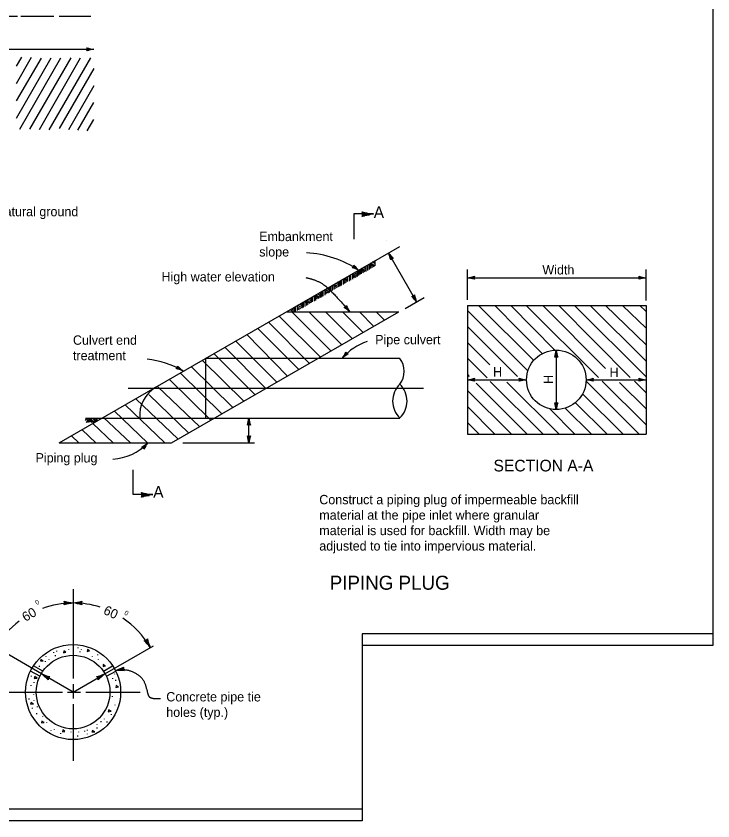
# Model space of a CAD drawing. Extents: x 0 to 390, y 0 to 265.
# Drawn here: x 241.1 to 390, y 0 to 172.1 of the extents above; entities that cross this region are included whole.
import ezdxf

# ---------------------------------------------------------------- set-up
doc = ezdxf.new("R2010")
doc.units = 0
doc.layers.add('D_Details', color=7, linetype='Continuous')
doc.layers.add('Default', color=7, linetype='Continuous')

msp = doc.modelspace()

# ---------------------------------------------------------------- linework, layer by layer
at = {"layer": 'D_Details'}
for p, q in [((234.15, 172.1), (241.35, 172.1)), ((242.05, 172.1), (249.15, 172.1)), ((250.25, 172.1), (257.05, 172.1)), ((223.85, 165), (257.65, 165)), ((241.15, 157.7), (244.35, 163.3)), ((241.15, 161.4), (242.25, 163.3)), ((241.15, 150.3), (248.55, 163.2)), ((241.15, 154), (246.45, 163.1)), ((241.85, 147.9), (250.65, 163.2)), ((252.75, 163.2), (243.95, 147.9)), ((254.75, 163.1), (245.95, 147.8)), ((256.95, 163.2), (248.05, 147.8)), ((257.65, 160.9), (250.25, 148.1)), ((257.65, 157.2), (252.25, 147.8)), ((254.25, 147.7), (257.65, 153.6)), ((256.25, 147.6), (257.65, 150)), ((320.23, 124.21), (320.23, 124.21)), ((250.27, 80.82), (323.11, 122.82)), ((320.67, 121.41), (326.67, 111.02)), ((316.21, 117.72), (316.21, 118.92)), ((316.61, 117.92), (316.61, 119.12)), ((316.91, 118.12), (316.91, 119.32)), ((317.81, 118.72), (316.91, 119.22)), ((317.61, 118.52), (316.91, 118.92)), ((317.81, 119.12), (317.21, 119.52)), ((317.81, 119.52), (317.51, 119.62)), ((317.81, 118.72), (317.81, 119.82)), ((313.91, 116.82), (313.31, 117.22)), ((314.01, 117.22), (313.71, 117.42)), ((314.01, 116.42), (314.01, 117.62)), ((314.31, 116.62), (314.31, 117.72)), ((314.61, 116.82), (314.61, 117.92)), ((314.91, 117.02), (314.91, 118.12)), ((315.91, 117.62), (314.91, 118.12)), ((315.61, 117.42), (314.91, 117.82)), ((315.31, 117.22), (315.01, 117.42)), ((315.91, 118.02), (315.31, 118.32)), ((315.91, 118.42), (315.61, 118.52)), ((315.91, 117.52), (315.91, 118.72)), ((317.31, 118.32), (316.91, 118.52)), ((337.52, 111.46), (337.52, 117.91)), ((375.72, 111.26), (375.72, 117.91)), ((310.01, 114.22), (310.01, 115.32)), ((310.31, 114.32), (310.31, 115.42)), ((310.61, 114.52), (310.61, 115.72)), ((311.01, 114.72), (311.01, 115.82)), ((311.91, 115.32), (311.01, 115.82)), ((311.71, 115.12), (311.01, 115.52)), ((311.91, 115.72), (311.31, 116.02)), ((311.91, 116.12), (311.71, 116.22)), ((311.91, 115.32), (311.91, 116.42)), ((312.01, 116.42), (312.01, 116.42)), ((312.31, 115.42), (312.31, 116.62)), ((312.61, 115.62), (312.61, 116.82)), ((313.01, 115.82), (313.01, 117.02)), ((314.01, 116.42), (313.01, 117.02)), ((313.71, 116.22), (313.01, 116.62)), ((313.41, 116.12), (313.01, 116.32)), ((337.52, 116.14), (375.72, 116.14)), ((307.11, 112.42), (307.11, 113.62)), ((308.01, 113.02), (307.11, 113.62)), ((308.01, 113.52), (307.41, 113.82)), ((308.01, 113.82), (307.81, 114.02)), ((308.01, 113.02), (308.01, 114.22)), ((308.31, 113.22), (308.31, 114.32)), ((308.71, 113.42), (308.71, 114.52)), ((309.01, 113.62), (309.01, 114.72)), ((310.01, 114.22), (309.01, 114.72)), ((309.71, 114.02), (309.01, 114.42)), ((309.41, 113.82), (309.01, 114.02)), ((310.01, 114.62), (309.41, 114.92)), ((310.01, 115.02), (309.71, 115.12)), ((311.41, 114.92), (311.01, 115.22)), ((304.11, 110.82), (304.11, 111.92)), ((304.41, 111.02), (304.41, 112.02)), ((304.81, 111.12), (304.81, 112.32)), ((305.11, 111.32), (305.11, 112.52)), ((306.11, 111.92), (305.11, 112.42)), ((305.81, 111.72), (305.11, 112.12)), ((306.01, 112.32), (305.51, 112.72)), ((306.11, 112.72), (305.81, 112.92)), ((306.11, 111.92), (306.11, 113.02)), ((306.11, 113.02), (306.11, 113.02)), ((306.41, 112.02), (306.41, 113.22)), ((306.71, 112.22), (306.71, 113.42)), ((307.81, 112.82), (307.11, 113.22)), ((307.41, 112.72), (307.11, 112.92)), ((324.19, 109.59), (328.29, 111.95)), ((301.21, 109.12), (301.21, 110.22)), ((302.21, 109.72), (301.21, 110.22)), ((302.21, 110.12), (301.61, 110.42)), ((302.21, 110.42), (301.91, 110.62)), ((302.21, 109.62), (302.21, 110.82)), ((302.51, 109.82), (302.51, 110.92)), ((302.81, 110.02), (302.81, 111.12)), ((303.21, 110.22), (303.11, 111.32)), ((303.81, 110.62), (303.11, 111.02)), ((304.11, 110.82), (303.21, 111.32)), ((303.51, 110.42), (303.21, 110.72)), ((304.11, 111.22), (303.51, 111.52)), ((304.11, 111.62), (303.81, 111.72)), ((305.51, 111.62), (305.11, 111.82)), ((337.52, 110.25), (337.52, 82.73)), ((337.52, 110.25), (375.72, 110.25)), ((339.89, 110.25), (351.72, 98.43)), ((343.4, 110.25), (353.52, 99.93)), ((346.81, 110.25), (356.22, 100.63)), ((350.09, 110.25), (365.52, 94.83)), ((353.66, 110.25), (367.02, 96.73)), ((357.04, 110.25), (372.32, 94.83)), ((360.39, 110.25), (375.72, 94.93)), ((363.79, 110.25), (375.72, 98.33)), ((367.02, 110.25), (375.72, 101.83)), ((370.68, 110.25), (375.72, 105.38)), ((374.35, 110.25), (375.72, 108.93)), ((375.72, 110.25), (375.72, 82.73)), ((274.3, 80.82), (322.9, 108.84)), ((298.88, 108.84), (322.9, 108.84)), ((300.21, 108.92), (299.61, 109.32)), ((300.21, 109.32), (299.91, 109.52)), ((300, 108.84), (308.38, 100.47)), ((300.21, 109.62), (300.21, 109.62)), ((300.51, 108.72), (300.51, 109.82)), ((300.81, 108.92), (300.81, 110.02)), ((301.91, 109.52), (301.21, 109.82)), ((301.61, 109.32), (301.21, 109.52)), ((303.61, 108.84), (310.66, 101.79)), ((307.22, 108.84), (312.95, 103.11)), ((310.82, 108.84), (315.24, 104.43)), ((314.43, 108.84), (317.53, 105.75)), ((318.03, 108.84), (319.81, 107.06)), ((337.52, 109.13), (350.42, 96.23)), ((297.3, 107.94), (306.09, 99.15)), ((292.71, 105.32), (301.51, 96.51)), ((295.02, 106.62), (303.8, 97.83)), ((337.52, 105.73), (348.22, 95.03)), ((290.41, 104.02), (299.09, 95.12)), ((288.01, 102.62), (296.82, 93.81)), ((337.52, 102.33), (342.32, 97.53)), ((283.31, 99.92), (292.13, 91.1)), ((285.71, 101.22), (294.31, 92.62)), ((356.52, 100.63), (356.52, 87.93)), ((280.93, 98.49), (289.76, 89.73)), ((281.51, 98.92), (305.68, 98.92)), ((281.51, 98.92), (281.51, 86.12)), ((305.68, 98.92), (323.11, 98.92)), ((337.52, 98.93), (341.72, 94.73)), ((278.57, 97.13), (287.4, 88.37)), ((276.2, 95.77), (285.05, 87.02)), ((337.52, 95.43), (337.92, 95.03)), ((273.81, 94.39), (282.69, 85.66)), ((337.52, 94.33), (350.12, 94.33)), ((339.42, 93.63), (350.32, 82.73)), ((342.42, 93.93), (353.72, 82.73)), ((345.92, 93.83), (357.12, 82.73)), ((362.92, 94.33), (375.72, 94.33)), ((362.92, 94.03), (374.22, 82.73)), ((366.32, 94.03), (375.72, 84.73)), ((370.02, 93.73), (375.72, 88.13)), ((373.22, 94.03), (375.72, 91.53)), ((265, 92.52), (328.11, 92.52)), ((271.27, 92.93), (280.3, 84.28)), ((337.52, 92.03), (346.92, 82.73)), ((362.12, 91.33), (370.82, 82.73)), ((266.67, 90.27), (275.7, 81.63)), ((269.51, 91.09), (278, 82.95)), ((264.37, 88.95), (272.85, 80.82)), ((337.52, 88.63), (343.42, 82.73)), ((355.12, 88.13), (360.52, 82.73)), ((358.42, 88.23), (364.02, 82.73)), ((360.62, 89.43), (367.42, 82.73)), ((255.91, 85.62), (256.21, 86.12)), ((255.91, 86.12), (255.91, 86.12)), ((255.91, 86.12), (259.46, 86.12)), ((256.11, 85.22), (256.61, 86.12)), ((256.41, 85.22), (257.01, 86.12)), ((257.61, 85.22), (257.01, 86.12)), ((257.81, 85.52), (257.51, 86.12)), ((257.61, 85.22), (258.11, 86.12)), ((258.01, 85.92), (257.81, 86.12)), ((257.91, 85.22), (258.51, 86.12)), ((259.46, 86.12), (283.49, 86.12)), ((259.77, 86.29), (265.48, 80.82)), ((262.07, 87.62), (269.17, 80.82)), ((283.49, 86.12), (323.11, 86.12)), ((290.82, 80.82), (290.82, 86.12)), ((256.91, 85.22), (256.71, 85.52)), ((257.31, 85.22), (256.81, 85.92)), ((257.47, 84.97), (261.8, 80.82)), ((337.52, 85.23), (340.02, 82.73)), ((255.17, 83.64), (258.11, 80.82)), ((337.52, 82.73), (375.72, 82.73)), ((252.87, 82.31), (254.43, 80.82)), ((250.27, 80.82), (274.3, 80.82)), ((276.67, 80.82), (292.02, 80.82)), ((253.25, 49.55), (253.25, 30.45)), ((246.45, 31.45), (235.25, 37.95)), ((249.75, 36.25), (249.75, 36.35)), ((252.35, 36.65), (252.35, 36.75)), ((254.35, 36.95), (254.35, 37.05)), ((254.75, 36.05), (254.75, 36.25)), ((255.05, 36.65), (255.05, 36.75)), ((260.05, 31.45), (270.45, 37.45)), ((247.45, 35.05), (247.45, 35.15)), ((248.15, 34.45), (248.15, 34.55)), ((249.15, 35.95), (249.15, 36.05)), ((249.45, 35.25), (249.45, 35.45)), ((257.35, 35.05), (257.35, 35.15)), ((258.55, 35.45), (258.55, 35.55)), ((258.65, 34.45), (258.65, 34.55)), ((246.75, 32.05), (244.75, 33.15)), ((246.05, 32.95), (246.05, 33.15)), ((247.35, 34.05), (247.35, 34.15)), ((259.75, 32.05), (261.65, 33.15)), ((246.15, 30.95), (244.15, 32.05)), ((244.35, 30.85), (244.35, 31.05)), ((253.25, 27.55), (246.45, 31.45)), ((253.25, 27.55), (260.05, 31.45)), ((260.35, 30.95), (262.35, 32.05)), ((262.15, 31.35), (262.15, 31.45)), ((244.95, 29.55), (244.95, 29.65)), ((261.75, 30.35), (261.75, 30.55)), ((262.35, 29.95), (262.35, 30.15)), ((239.55, 27.55), (250.95, 27.55)), ((244.25, 28.85), (244.25, 29.05)), ((252.05, 27.55), (253.25, 27.55)), ((253.25, 29.25), (253.25, 26.15)), ((253.55, 27.55), (254.85, 27.55)), ((255.95, 27.55), (267.55, 27.55)), ((243.85, 25.95), (243.85, 26.15)), ((244.85, 26.95), (244.85, 27.05)), ((244.95, 25.75), (244.95, 25.85)), ((261.65, 26.55), (261.65, 26.65)), ((244.55, 24.05), (244.55, 24.15)), ((245.65, 24.35), (245.65, 24.45)), ((253.25, 24.95), (253.25, 12.85)), ((262.25, 24.75), (262.25, 24.85)), ((245.45, 22.85), (245.45, 23.05)), ((261.45, 22.65), (261.45, 22.85)), ((246.75, 22.25), (246.75, 22.35)), ((247.65, 20.95), (247.65, 21.05)), ((259.25, 21.15), (259.25, 21.35)), ((259.95, 21.75), (259.95, 21.85)), ((260.55, 21.05), (260.55, 21.25)), ((248.55, 19.25), (248.55, 19.35)), ((249.25, 19.45), (249.25, 19.55)), ((252.85, 18.95), (252.85, 19.05)), ((254.45, 18.95), (254.45, 19.05)), ((255.75, 19.15), (255.75, 19.25)), ((256.35, 19.35), (256.35, 19.45)), ((258.35, 20.55), (258.35, 20.65)), ((258.35, 19.75), (258.35, 19.95)), ((250.65, 18.65), (250.65, 18.75)), ((254.25, 18.05), (254.25, 18.25)), ((256.35, 18.55), (256.35, 18.65))]:
    msp.add_line(p, q, dxfattribs=at)
for points in [[(317.43, 129.81), (313.23, 129.81), (313.23, 124.41)], [(315.03, 130.21), (315.13, 130.21)], [(315.03, 130.11), (315.53, 130.11)], [(315.03, 129.41), (315.53, 129.41)], [(315.03, 129.31), (315.13, 129.31)], [(315.13, 130.01), (316.03, 130.01)], [(315.13, 129.91), (316.63, 129.91)], [(315.13, 129.81), (315.13, 129.81), (317.43, 129.81), (317.43, 129.81)], [(315.13, 129.61), (316.63, 129.61)], [(315.13, 129.51), (316.03, 129.51)], [(270.28, 69.79), (266.08, 69.79), (266.08, 75.09)], [(267.88, 70.19), (267.98, 70.19)], [(267.88, 70.09), (268.38, 70.09)], [(267.88, 69.39), (268.38, 69.39)], [(267.88, 69.29), (267.98, 69.29)], [(267.98, 69.99), (268.88, 69.99)], [(267.98, 69.89), (269.48, 69.89)], [(267.98, 69.79), (267.98, 69.79), (270.28, 69.79), (270.28, 69.79)], [(267.98, 69.59), (269.48, 69.59)], [(267.98, 69.49), (268.88, 69.49)]]:
    msp.add_lwpolyline(points, dxfattribs=at)
for points in [[(251.15, 35.95), (251.65, 36.05), (251.25, 36.35)], [(256.25, 36.25), (256.75, 36.35), (256.35, 36.65)], [(246.25, 34.25), (246.85, 34.25), (246.35, 34.55)], [(259.65, 33.05), (260.15, 33.15), (259.65, 33.45)], [(244.95, 30.45), (245.55, 30.55), (245.05, 30.85)], [(262.35, 28.55), (262.95, 28.65), (262.45, 28.95)], [(244.15, 24.95), (244.75, 25.05), (244.25, 25.35)], [(260.75, 23.35), (261.35, 23.45), (260.85, 23.75)], [(246.45, 20.95), (247.05, 21.05), (246.55, 21.35)], [(250.95, 19.05), (251.45, 19.15), (251.05, 19.45)], [(257.25, 19.05), (257.85, 19.05), (257.35, 19.35)]]:
    msp.add_lwpolyline(points, close=True, dxfattribs=at)
for centre, radius in [((356.52, 94.32), 6.36), ((253.24, 27.55), 10.16), ((253.24, 27.55), 7.87)]:
    msp.add_circle(centre, radius, dxfattribs=at)
for centre, radius, start, end in [((255.53, 165), 0.699, 333.215, 26.785), ((259.22, 176.14), 11.25, 254.1865, 262), ((259.22, 153.86), 11.25, 98, 105.8117), ((259.22, 176.14), 11.35, 254.5699, 258.999), ((259.22, 153.86), 11.35, 101.001, 105.4301), ((259.22, 176.14), 11.45, 254.8291, 256.6406), ((259.22, 153.86), 11.45, 103.3594, 105.1709), ((314, 129.76), 1.13, 333.215, 26.785), ((319.95, 147.73), 18.14, 254.1865, 262), ((319.95, 111.8), 18.14, 98, 105.8117), ((302.07, 99.65), 21.83, 55.8846, 87.2459), ((310.21, 117.28), 11.25, 13.7646, 21.5781), ((329.59, 128.27), 11.25, 217.5781, 225.3898), ((329.59, 128.27), 11.35, 220.5791, 225.0082), ((310.21, 117.28), 11.35, 14.148, 18.5771), ((329.59, 128.27), 11.45, 222.9374, 224.749), ((310.21, 117.28), 11.45, 14.4072, 16.2187), ((312.55, 118.91), 0.699, 299.0996, 352.6696), ((321.86, 126.06), 11.25, 220.0711, 227.8846), ((321.72, 119.57), 0.699, 92.7931, 146.3631), ((309.36, 107.62), 11.25, 63.8846, 71.6963), ((309.36, 107.62), 11.35, 66.8856, 71.3147), ((309.36, 107.62), 11.45, 69.244, 71.0555), ((321.86, 126.06), 11.45, 220.7137, 222.5252), ((321.86, 126.06), 11.35, 220.4545, 224.8836), ((335.95, 127.28), 11.25, 278, 285.8117), ((335.95, 105), 11.25, 74.1865, 82), ((335.95, 127.28), 11.35, 281.001, 285.4301), ((335.95, 105), 11.35, 74.5699, 78.999), ((335.95, 127.28), 11.45, 283.3594, 285.1709), ((335.95, 105), 11.45, 74.8291, 76.6406), ((339.64, 116.14), 0.699, 153.215, 206.785), ((373.59, 116.14), 0.699, 333.215, 26.785), ((377.28, 127.28), 11.25, 254.1865, 262), ((377.28, 105), 11.25, 98, 105.8117), ((377.28, 127.28), 11.35, 254.5699, 258.999), ((377.28, 105), 11.35, 101.001, 105.4301), ((377.28, 127.28), 11.45, 254.8291, 256.6406), ((377.28, 105), 11.45, 103.3594, 105.1709), ((325.6, 112.86), 0.699, 273.2016, 326.7716), ((317.8, 104.09), 11.25, 37.9866, 45.7983), ((317.8, 104.09), 11.35, 40.9876, 45.4167), ((317.8, 104.09), 11.45, 43.346, 45.1575), ((337.1, 115.23), 11.45, 194.8157, 196.6273), ((337.1, 115.23), 11.35, 194.5565, 198.9856), ((337.1, 115.23), 11.25, 194.1732, 201.9866), ((310.98, 110.45), 0.699, 284.266, 337.836), ((321.81, 114.98), 11.25, 205.2375, 213.051), ((305.01, 100.35), 11.25, 49.051, 56.8627), ((305.01, 100.35), 11.35, 52.052, 56.4811), ((305.01, 100.35), 11.45, 54.4104, 56.2219), ((321.81, 114.98), 11.45, 205.8801, 207.6917), ((321.81, 114.98), 11.35, 205.6209, 210.05), ((319.39, 91.96), 11.04, 107.2977, 140.6943), ((301.23, 104.8), 11.25, 328.6943, 336.506), ((318.47, 90.68), 11.25, 124.8809, 132.6943), ((301.23, 104.8), 11.35, 331.6953, 336.1244), ((318.47, 90.68), 11.35, 125.2642, 129.6933), ((301.23, 104.8), 11.45, 334.0537, 335.8652), ((318.47, 90.68), 11.45, 125.5234, 127.335), ((312.19, 100.6), 0.699, 203.9093, 257.4793), ((345.38, 102.2), 11.25, 344.1865, 352), ((345.38, 102.2), 11.35, 344.5699, 348.999), ((367.66, 102.2), 11.25, 188, 195.8117), ((367.66, 102.2), 11.35, 191.001, 195.4301), ((266.75, 78.3), 20.54, 60.9848, 83.526), ((319.5, 96.14), 4.52, 322.6781, 37.3219), ((356.52, 98.51), 0.699, 63.215, 116.785), ((345.38, 102.2), 11.45, 344.8291, 346.6406), ((367.66, 102.2), 11.45, 193.3594, 195.1709), ((274.86, 97.29), 0.699, 304.1998, 357.7698), ((272.68, 85.76), 11.25, 68.9848, 76.7965), ((272.68, 85.76), 11.35, 71.9858, 76.4149), ((272.68, 85.76), 11.45, 74.3442, 76.1558), ((283.49, 105.24), 11.45, 225.8139, 227.6255), ((283.49, 105.24), 11.35, 225.5548, 229.9838), ((283.49, 105.24), 11.25, 225.1714, 232.9848), ((326.51, 89.78), 4.97, 133.3358, 226.6642), ((319.57, 89.78), 5.05, 314.2869, 45.7131), ((335.95, 105.47), 11.25, 278, 285.8117), ((335.95, 105.47), 11.25, 278, 285.8117), ((335.95, 83.19), 11.25, 74.1865, 82), ((335.95, 83.19), 11.25, 74.1865, 82), ((335.95, 105.47), 11.35, 281.001, 285.4301), ((335.95, 105.47), 11.35, 281.001, 285.4301), ((335.95, 83.19), 11.35, 74.5699, 78.999), ((335.95, 83.19), 11.35, 74.5699, 78.999), ((335.95, 105.47), 11.45, 283.3594, 285.1709), ((335.95, 105.47), 11.45, 283.3594, 285.1709), ((335.95, 83.19), 11.45, 74.8291, 76.6406), ((335.95, 83.19), 11.45, 74.8291, 76.6406), ((339.64, 94.33), 0.699, 153.215, 206.785), ((339.64, 94.33), 0.699, 153.215, 206.785), ((347.99, 94.33), 0.699, 333.215, 26.785), ((351.68, 105.47), 11.25, 254.1865, 262), ((351.68, 83.19), 11.25, 98, 105.8117), ((351.68, 105.47), 11.35, 254.5699, 258.999), ((351.68, 83.19), 11.35, 101.001, 105.4301), ((351.68, 105.47), 11.45, 254.8291, 256.6406), ((351.68, 83.19), 11.45, 103.3594, 105.1709), ((361.35, 105.47), 11.25, 278, 285.8117), ((361.35, 105.47), 11.25, 278, 285.8117), ((361.35, 83.19), 11.25, 74.1865, 82), ((361.35, 83.19), 11.25, 74.1865, 82), ((361.35, 105.47), 11.35, 281.001, 285.4301), ((361.35, 105.47), 11.35, 281.001, 285.4301), ((361.35, 83.19), 11.35, 74.5699, 78.999), ((361.35, 83.19), 11.35, 74.5699, 78.999), ((361.35, 105.47), 11.45, 283.3594, 285.1709), ((361.35, 105.47), 11.45, 283.3594, 285.1709), ((361.35, 83.19), 11.45, 74.8291, 76.6406), ((361.35, 83.19), 11.45, 74.8291, 76.6406), ((365.04, 94.33), 0.699, 153.215, 206.785), ((365.04, 94.33), 0.699, 153.215, 206.785), ((373.59, 94.33), 0.699, 333.215, 26.785), ((377.28, 105.47), 11.25, 254.1865, 262), ((373.59, 94.33), 0.699, 333.215, 26.785), ((377.28, 105.47), 11.25, 254.1865, 262), ((377.28, 83.19), 11.25, 98, 105.8117), ((377.28, 83.19), 11.25, 98, 105.8117), ((377.28, 105.47), 11.35, 254.5699, 258.999), ((377.28, 105.47), 11.35, 254.5699, 258.999), ((377.28, 83.19), 11.35, 101.001, 105.4301), ((377.28, 83.19), 11.35, 101.001, 105.4301), ((377.28, 105.47), 11.45, 254.8291, 256.6406), ((377.28, 105.47), 11.45, 254.8291, 256.6406), ((377.28, 83.19), 11.45, 103.3594, 105.1709), ((377.28, 83.19), 11.45, 103.3594, 105.1709), ((274.45, 86.71), 6.99, 120.0001, 184.8262), ((356.52, 90.05), 0.699, 243.215, 296.785), ((345.38, 86.36), 11.25, 8, 15.8117), ((345.38, 86.36), 11.35, 11.001, 15.4301), ((345.38, 86.36), 11.45, 13.3594, 15.1709), ((367.66, 86.36), 11.25, 164.1865, 172), ((367.66, 86.36), 11.35, 164.5699, 168.999), ((367.66, 86.36), 11.45, 164.8291, 166.6406), ((279.68, 87.68), 11.25, 344.1865, 352), ((301.96, 87.68), 11.25, 188, 195.8117), ((290.82, 83.99), 0.699, 63.215, 116.785), ((279.68, 87.68), 11.35, 344.5699, 348.999), ((279.68, 87.68), 11.45, 344.8291, 346.6406), ((301.96, 87.68), 11.35, 191.001, 195.4301), ((301.96, 87.68), 11.45, 193.3594, 195.1709), ((290.82, 82.94), 0.699, 243.215, 296.785), ((279.68, 79.25), 11.25, 8, 15.8117), ((279.68, 79.25), 11.35, 11.001, 15.4301), ((279.68, 79.25), 11.45, 13.3594, 15.1709), ((301.96, 79.25), 11.25, 164.1865, 172), ((301.96, 79.25), 11.35, 164.5699, 168.999), ((301.96, 79.25), 11.45, 164.8291, 166.6406), ((261.13, 88.38), 11.03, 273.067, 316.7341), ((262.13, 89.59), 11.25, 300.9206, 308.7341), ((267.71, 79.27), 0.699, 19.9491, 73.519), ((262.13, 89.59), 11.35, 301.304, 305.7331), ((262.13, 89.59), 11.45, 301.5631, 303.3747), ((278.36, 74.32), 11.45, 150.0934, 151.905), ((278.36, 74.32), 11.35, 147.735, 152.1641), ((278.36, 74.32), 11.25, 144.734, 152.5457), ((266.85, 69.75), 1.13, 333.215, 26.785), ((272.8, 87.71), 18.14, 254.1865, 262), ((272.8, 51.78), 18.14, 98, 105.8117), ((253.24, 27.55), 19.05, 90.0703, 110.1632), ((255.16, 60.53), 14.06, 254.2568, 262.0703), ((250.56, 46.6), 0.874, 333.2853, 26.8553), ((255.19, 32.68), 14.06, 98.0703, 105.882), ((255.16, 60.53), 14.19, 254.6402, 259.0693), ((255.19, 32.68), 14.19, 101.0713, 105.5004), ((255.16, 60.53), 14.31, 254.8994, 256.7109), ((255.19, 32.68), 14.31, 103.4297, 105.2412), ((251.3, 60.53), 14.06, 277.9729, 285.7846), ((253.24, 27.55), 19.05, 72.2166, 89.9729), ((251.28, 32.68), 14.06, 74.1594, 81.9729), ((251.3, 60.53), 14.19, 280.9739, 285.403), ((251.28, 32.68), 14.19, 74.5428, 78.9719), ((251.3, 60.53), 14.31, 283.3322, 285.1438), ((251.28, 32.68), 14.31, 74.802, 76.6135), ((255.9, 46.6), 0.874, 153.1879, 206.7579), ((253.24, 27.55), 19.05, 30.1316, 56.1425), ((253.24, 27.55), 19.05, 127.2781, 150.0252), ((268.38, 39.41), 0.874, 273.3466, 326.9166), ((258.65, 28.43), 14.06, 38.1316, 45.9433), ((258.65, 28.43), 14.19, 41.1326, 45.5617), ((258.65, 28.43), 14.31, 43.491, 45.3025), ((282.74, 42.41), 14.31, 194.9607, 196.7722), ((282.74, 42.41), 14.19, 194.7015, 199.1306), ((282.74, 42.41), 14.06, 194.3181, 202.1316), ((257.6, 45.42), 14.06, 289.3099, 297.1216), ((257.6, 45.42), 14.19, 292.3109, 296.74), ((264.86, 32.67), 0.874, 164.5249, 218.0949), ((237.83, 20.34), 14.06, 44.351, 52.1645), ((251.68, 44.5), 14.06, 248.1645, 255.9761), ((251.68, 44.5), 14.19, 251.1655, 255.5945), ((237.83, 20.34), 14.19, 44.7344, 49.1635), ((254.82, 44.5), 14.06, 284.0221, 291.8355), ((254.82, 44.5), 14.19, 284.4055, 288.8345), ((268.68, 20.34), 14.19, 130.8365, 135.2656), ((268.68, 20.34), 14.06, 127.8355, 135.6472), ((263.07, 18.11), 14.06, 85.4965, 93.3099), ((263.07, 18.11), 14.19, 85.8799, 90.3089), ((257.6, 45.42), 14.31, 294.6693, 296.4809), ((263.07, 18.11), 14.31, 86.139, 87.9506), ((237.83, 20.34), 14.31, 44.9935, 46.8051), ((251.68, 44.5), 14.31, 253.5238, 255.3354), ((248.76, 30.13), 0.874, 123.3795, 176.9495), ((257.75, 30.13), 0.874, 3.0505, 56.6205), ((254.82, 44.5), 14.31, 284.6646, 286.4762), ((268.68, 20.34), 14.31, 133.1949, 135.0065)]:
    msp.add_arc(centre, radius, start, end, dxfattribs=at)
for points in [[(302.99, 116.17), (305.32, 115.73), (308.38, 113.55), (312.38, 108.84)], [(262.25, 32.15), (263.25, 32.35), (264.85, 32.35), (266.85, 31.55), (268.35, 30.15), (268.95, 28.25), (269.35, 26.55), (270.05, 26.25), (270.85, 26.15), (271.95, 26.15)]]:
    msp.add_open_spline(points, degree=2, dxfattribs=at)
at = {"layer": 'Default'}
for points in [[(0, 265), (326.25, 265), (326.25, 255), (390, 255), (390, 37.5), (315, 37.5), (315, 0), (0, 0)], [(0, 262.5), (326.25, 262.5), (326.25, 252.5), (390, 252.5), (390, 40), (315, 40), (315, 2.5), (0, 2.5)]]:
    msp.add_lwpolyline(points, close=True, dxfattribs=at)

# ---------------------------------------------------------------- texts
at = {"layer": 'D_Details'}
for s, height, p in [('Natural ground', 2, (236.66, 129.3)), ('A', 2.5, (317.49, 128.91)), ('Embankment', 2, (293.02, 123.99)), ('slope', 2, (293.02, 120.69)), ('Width', 2, (353.55, 116.85)), ('High water elevation', 2, (272.13, 115.36)), ('Culvert end', 2, (253.21, 101.82)), ('Pipe culvert', 2, (317.81, 101.92)), ('treatment', 2, (253.21, 98.52)), ('H', 2, (343.02, 95.03)), ('H', 2, (367.92, 94.93)), ('Piping plug', 2, (245.21, 76.65)), ('SECTION A-A', 2.5002, (343.1, 74.73)), ('A', 2.5, (270.35, 69.1)), ('Construct a piping plug of impermeable backfill ', 2, (305.86, 67.71)), ('material at the pipe inlet where granular ', 2, (305.86, 64.41)), ('material is used for backfill. Width may be', 2, (305.86, 61.11)), ('adjusted to tie into impervious material.', 2, (305.86, 57.81)), ('PIPING PLUG', 3, (308.09, 49.43)), ('Concrete pipe tie', 2, (273.15, 25.55)), ('holes (typ.)', 2, (273.15, 22.25))]:
    msp.add_text(s, height=height, dxfattribs=at).set_placement(p)
for s, rotation, p in [('H', 90, (355.82, 93.43)), ('60', 30, (243.05, 42.55)), ('60', 335, (259.55, 44.35))]:
    msp.add_text(s, height=2, rotation=rotation, dxfattribs=at).set_placement(p)
at = {"layer": 'Default'}
for rotation, p in [(31.6908, (245.51, 46.12)), (327.9076, (264.06, 44.23))]:
    msp.add_text('0', height=1, rotation=rotation, dxfattribs=at).set_placement(p)

doc.saveas('drawing.dxf')
